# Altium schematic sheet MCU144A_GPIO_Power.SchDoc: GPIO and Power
size 431 x 279 mm; Date: Not shown in title block; ApprovedBy: Not shown in title block; CheckedBy: Not shown in title block; Author: Not shown in title block; CompanyName: Not shown in title block; DrawnBy: Gustavo Martinez; Engineer: Not shown in title block; Organization: Not shown in title block; Address1: Not shown in title block; Address2: Not shown in title block; Address3: Not shown in title block; Address4: Not shown in title block; DocumentNumber: 8; Revision: Use project parameter SCH_Rev; SheetNumber: 2; SheetTotal: 8; PageSetup: Record=PageOptions¦CenterHorizontal=True¦CenterVertical=True¦PrintScale=1.00¦XCorrection=1.00¦YCorrection=1.00¦PrintKind=0¦BorderSize=5000000¦LeftOffset=0¦BottomOffset=0¦Orientation=2¦PaperLength=1000¦PaperWidth=1000¦Scale=100¦PaperSource=15¦PrintQuality=600¦MediaType=1¦DitherType=10¦PaperKind=Letter¦PrintScaleMode=1
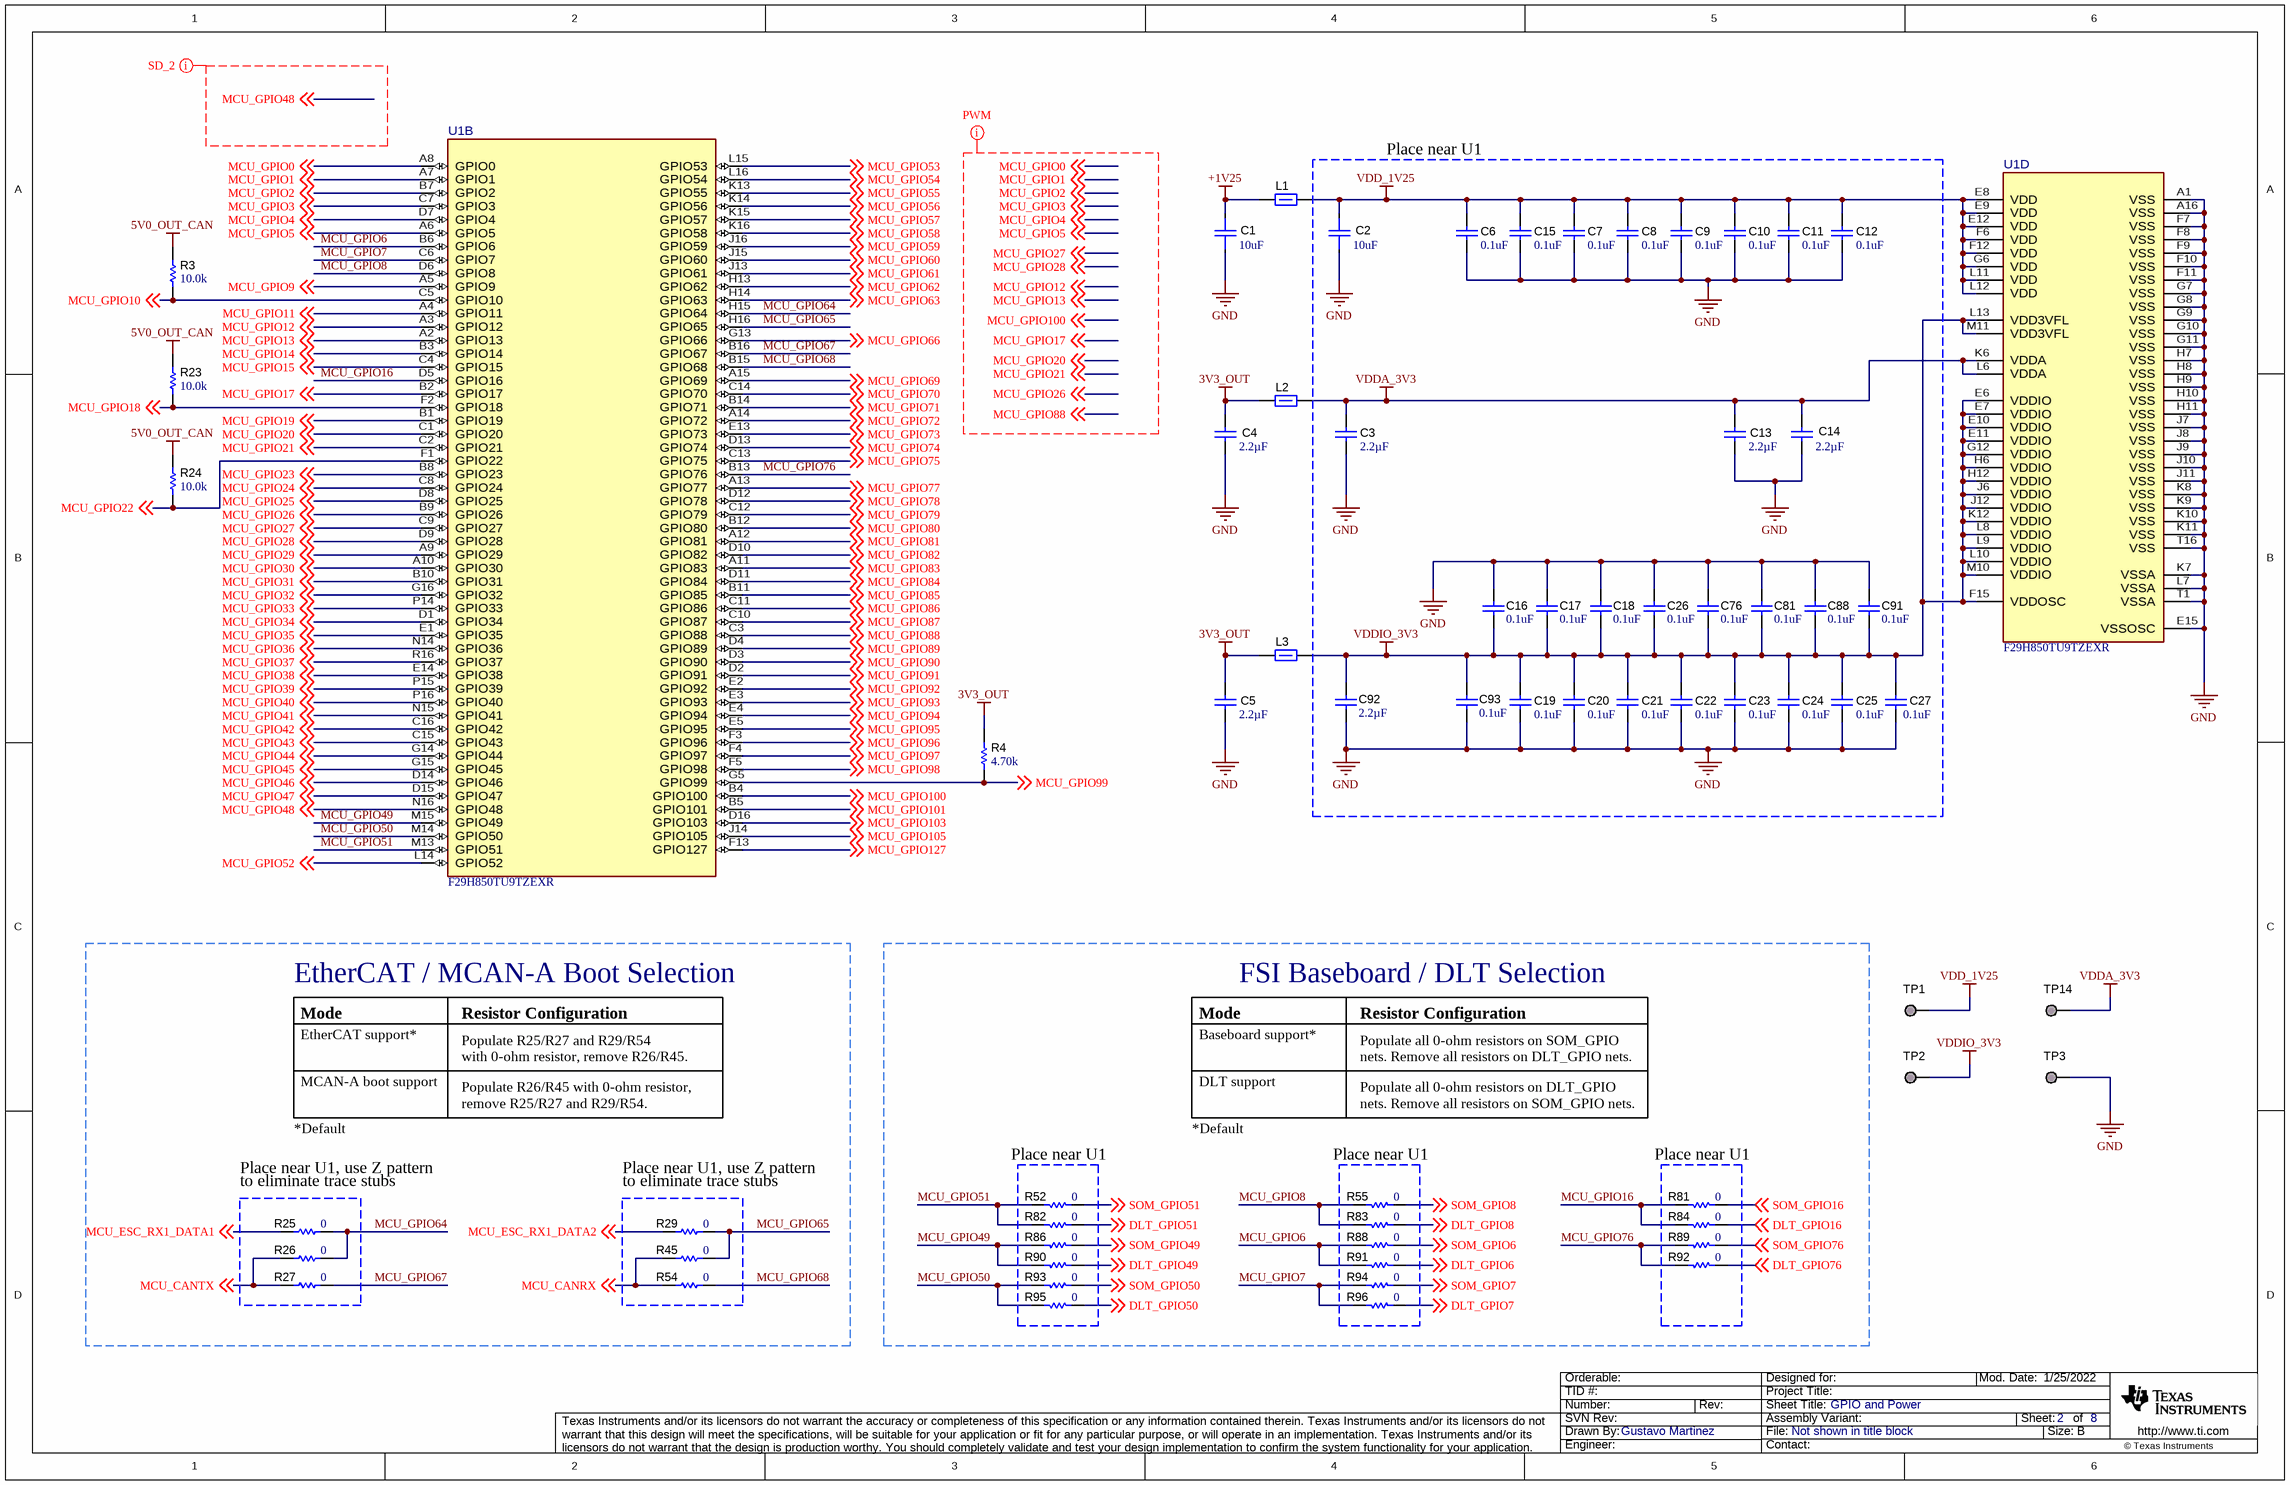
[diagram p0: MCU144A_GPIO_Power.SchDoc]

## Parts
C1  ValueDisplayed: 10uF  [FP-GRM155R61A106ME18D_0402-MFG]  (hidden comment: GRM155R61A106ME18D)
C2  ValueDisplayed: 10uF  [FP-GRM155R61A106ME18D_0402-MFG]  (hidden comment: GRM155R61A106ME18D)
C3  ValueDisplayed: 2.2µF  [0402]  (hidden comment: GRM155R61E225ME15D)
C4  ValueDisplayed: 2.2µF  [0402]  (hidden comment: GRM155R61E225ME15D)
C5  ValueDisplayed: 2.2µF  [0402]  (hidden comment: GRM155R61E225ME15D)
C6  ValueDisplayed: 0.1uF  [0402]  (hidden comment: GRM155R71E104KE14D)
C7  ValueDisplayed: 0.1uF  [0402]  (hidden comment: GRM155R71E104KE14D)
C8  ValueDisplayed: 0.1uF  [0402]  (hidden comment: GRM155R71E104KE14D)
C9  ValueDisplayed: 0.1uF  [0402]  (hidden comment: GRM155R71E104KE14D)
C10  ValueDisplayed: 0.1uF  [0402]  (hidden comment: GRM155R71E104KE14D)
C11  ValueDisplayed: 0.1uF  [0402]  (hidden comment: GRM155R71E104KE14D)
C12  ValueDisplayed: 0.1uF  [0402]  (hidden comment: GRM155R71E104KE14D)
C13  ValueDisplayed: 2.2µF  [0402]  (hidden comment: GRM155R61E225ME15D)
C14  ValueDisplayed: 2.2µF  [0402]  (hidden comment: GRM155R61E225ME15D)
C15  ValueDisplayed: 0.1uF  [0402]  (hidden comment: GRM155R71E104KE14D)
C16  ValueDisplayed: 0.1uF  [0402]  (hidden comment: GRM155R71E104KE14D)
C17  ValueDisplayed: 0.1uF  [0402]  (hidden comment: GRM155R71E104KE14D)
C18  ValueDisplayed: 0.1uF  [0402]  (hidden comment: GRM155R71E104KE14D)
C19  ValueDisplayed: 0.1uF  [0402]  (hidden comment: GRM155R71E104KE14D)
C20  ValueDisplayed: 0.1uF  [0402]  (hidden comment: GRM155R71E104KE14D)
C21  ValueDisplayed: 0.1uF  [0402]  (hidden comment: GRM155R71E104KE14D)
C22  ValueDisplayed: 0.1uF  [0402]  (hidden comment: GRM155R71E104KE14D)
C23  ValueDisplayed: 0.1uF  [0402]  (hidden comment: GRM155R71E104KE14D)
C24  ValueDisplayed: 0.1uF  [0402]  (hidden comment: GRM155R71E104KE14D)
C25  ValueDisplayed: 0.1uF  [0402]  (hidden comment: GRM155R71E104KE14D)
C26  ValueDisplayed: 0.1uF  [0402]  (hidden comment: GRM155R71E104KE14D)
C27  ValueDisplayed: 0.1uF  [0402]  (hidden comment: GRM155R71E104KE14D)
C76  ValueDisplayed: 0.1uF  [0402]  (hidden comment: GRM155R71E104KE14D)
C81  ValueDisplayed: 0.1uF  [0402]  (hidden comment: GRM155R71E104KE14D)
C88  ValueDisplayed: 0.1uF  [0402]  (hidden comment: GRM155R71E104KE14D)
C91  ValueDisplayed: 0.1uF  [0402]  (hidden comment: GRM155R71E104KE14D)
C92  ValueDisplayed: 2.2µF  [0402]  (hidden comment: GRM155R61E225ME15D)
C93  ValueDisplayed: 0.1uF  [0402]  (hidden comment: GRM155R71E104KE14D)
L1  BLM21PG221SN1D  [0805_HV]  (value not drawn)
L2  60ohm  [0603]  (value not drawn)
L3  60ohm  [0603]  (value not drawn)
R3  value 10.0k  [0402]  (hidden comment: AC0402FR-0710KL)
R4  ValueDisplayed: 4.70k  [0402]  (hidden comment: CRG0402F4K7)
R23  value 10.0k  [0402]  (hidden comment: AC0402FR-0710KL)
R24  value 10.0k  [0402]  (hidden comment: AC0402FR-0710KL)
R25  ValueDisplayed: 0  [0402]  (hidden comment: CRCW04020000Z0ED)
R26  ValueDisplayed: 0  [0402]  (hidden comment: CRCW04020000Z0ED)
R27  ValueDisplayed: 0  [0402]  (hidden comment: CRCW04020000Z0ED)
R29  ValueDisplayed: 0  [0402]  (hidden comment: CRCW04020000Z0ED)
R45  ValueDisplayed: 0  [0402]  (hidden comment: CRCW04020000Z0ED)
R52  ValueDisplayed: 0  [0402]  (hidden comment: CRCW04020000Z0ED)
R54  ValueDisplayed: 0  [0402]  (hidden comment: CRCW04020000Z0ED)
R55  ValueDisplayed: 0  [0402]  (hidden comment: CRCW04020000Z0ED)
R81  ValueDisplayed: 0  [0402]  (hidden comment: CRCW04020000Z0ED)
R82  ValueDisplayed: 0  [0402]  (hidden comment: CRCW04020000Z0ED)
R83  ValueDisplayed: 0  [0402]  (hidden comment: CRCW04020000Z0ED)
R84  ValueDisplayed: 0  [0402]  (hidden comment: CRCW04020000Z0ED)
R86  ValueDisplayed: 0  [0402]  (hidden comment: CRCW04020000Z0ED)
R88  ValueDisplayed: 0  [0402]  (hidden comment: CRCW04020000Z0ED)
R89  ValueDisplayed: 0  [0402]  (hidden comment: CRCW04020000Z0ED)
R90  ValueDisplayed: 0  [0402]  (hidden comment: CRCW04020000Z0ED)
R91  ValueDisplayed: 0  [0402]  (hidden comment: CRCW04020000Z0ED)
R92  ValueDisplayed: 0  [0402]  (hidden comment: CRCW04020000Z0ED)
R93  ValueDisplayed: 0  [0402]  (hidden comment: CRCW04020000Z0ED)
R94  ValueDisplayed: 0  [0402]  (hidden comment: CRCW04020000Z0ED)
R95  ValueDisplayed: 0  [0402]  (hidden comment: CRCW04020000Z0ED)
R96  ValueDisplayed: 0  [0402]  (hidden comment: CRCW04020000Z0ED)
TP1  CMP-0078143-4  [TESTPOINT]  (value not drawn)  (no BOM)
TP2  CMP-0078143-4  [TESTPOINT]  (value not drawn)  (no BOM)
TP3  CMP-0078143-4  [TESTPOINT]  (value not drawn)  (no BOM)
TP14  CMP-0078143-4  [TESTPOINT]  (value not drawn)  (no BOM)
U1  F29H850TU9TZEXR  [ZEX0256A-MFG]  (parts B,D of 4)

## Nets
3V3_OUT: C4.1 C5.1 L2.1 L3.1 R4.2
5V0_OUT_CAN: R3.2 R23.2 R24.2
+1V25: C1.2 L1.1
GND: C1.1 C2.1 C3.2 C4.2 C5.2 C6.2 C7.2 C8.2 C9.2 C10.2 C11.2 C12.2 C13.2 C14.2 C15.2 C16.2 C17.2 C18.2 C19.2 C20.2 C21.2 C22.2 C23.2 C24.2 C25.2 C26.2 C27.2 C76.2 C81.2 C88.2 C91.2 C92.1 C93.1 TP3.1 U1.A1(VSS) U1.A16(VSS) U1.E15(VSSOSC) U1.F7(VSS) U1.F8(VSS) U1.F9(VSS) U1.F10(VSS) U1.F11(VSS) U1.G7(VSS) U1.G8(VSS) U1.G9(VSS) U1.G10(VSS) U1.G11(VSS) U1.H7(VSS) U1.H8(VSS) U1.H9(VSS) U1.H10(VSS) U1.H11(VSS) U1.J7(VSS) U1.J8(VSS) U1.J9(VSS) U1.J10(VSS) U1.J11(VSS) U1.K7(VSSA) U1.K8(VSS) U1.K9(VSS) U1.K10(VSS) U1.K11(VSS) U1.L7(VSSA) U1.T1(VSSA) U1.T16(VSS)
VDD_1V25: C2.2 C6.1 C7.1 C8.1 C9.1 C10.1 C11.1 C12.1 C15.1 L1.2 TP1.1 U1.E8(VDD) U1.E9(VDD) U1.E12(VDD) U1.F6(VDD) U1.F12(VDD) U1.G6(VDD) U1.L11(VDD) U1.L12(VDD)
VDDA_3V3: C3.1 C13.1 C14.1 L2.2 TP14.1 U1.K6(VDDA) U1.L6(VDDA)
VDDIO_3V3: C16.1 C17.1 C18.1 C19.1 C20.1 C21.1 C22.1 C23.1 C24.1 C25.1 C26.1 C27.1 C76.1 C81.1 C88.1 C91.1 C92.2 C93.2 L3.2 TP2.1 U1.E6(VDDIO) U1.E7(VDDIO) U1.E10(VDDIO) U1.E11(VDDIO) U1.F15(VDDOSC) U1.G12(VDDIO) U1.H6(VDDIO) U1.H12(VDDIO) U1.J6(VDDIO) U1.J12(VDDIO) U1.K12(VDDIO) U1.L8(VDDIO) U1.L9(VDDIO) U1.L10(VDDIO) U1.L13(VDD3VFL) U1.M10(VDDIO) U1.M11(VDD3VFL)
DLT_GPIO6: R91.1 ; off-sheet DLT_GPIO6
DLT_GPIO7: R96.1 ; off-sheet DLT_GPIO7
DLT_GPIO8: R83.1 ; off-sheet DLT_GPIO8
DLT_GPIO16: R84.1 ; off-sheet DLT_GPIO16
DLT_GPIO49: R90.1 ; off-sheet DLT_GPIO49
DLT_GPIO50: R95.1 ; off-sheet DLT_GPIO50
DLT_GPIO51: R82.1 ; off-sheet DLT_GPIO51
DLT_GPIO76: R92.1 ; off-sheet DLT_GPIO76
MCU_CANRX: R45.1 R54.1 ; off-sheet MCU_CANRX
MCU_CANTX: R26.1 R27.1 ; off-sheet MCU_CANTX
MCU_ESC_RX1_DATA1: R25.1 ; off-sheet MCU_ESC_RX1_DATA1
MCU_ESC_RX1_DATA2: R29.1 ; off-sheet MCU_ESC_RX1_DATA2
MCU_GPIO0: U1.A8(GPIO0) ; off-sheet MCU_GPIO0
MCU_GPIO1: U1.A7(GPIO1) ; off-sheet MCU_GPIO1
MCU_GPIO2: U1.B7(GPIO2) ; off-sheet MCU_GPIO2
MCU_GPIO3: U1.C7(GPIO3) ; off-sheet MCU_GPIO3
MCU_GPIO4: U1.D7(GPIO4) ; off-sheet MCU_GPIO4
MCU_GPIO5: U1.A6(GPIO5) ; off-sheet MCU_GPIO5
MCU_GPIO6: R88.2 R91.2 U1.B6(GPIO6)
MCU_GPIO7: R94.2 R96.2 U1.C6(GPIO7)
MCU_GPIO8: R55.2 R83.2 U1.D6(GPIO8)
MCU_GPIO9: U1.A5(GPIO9) ; off-sheet MCU_GPIO9
MCU_GPIO10: R3.1 U1.C5(GPIO10) ; off-sheet MCU_GPIO10
MCU_GPIO11: U1.A4(GPIO11) ; off-sheet MCU_GPIO11
MCU_GPIO12: U1.A3(GPIO12) ; off-sheet MCU_GPIO12
MCU_GPIO13: U1.A2(GPIO13) ; off-sheet MCU_GPIO13
MCU_GPIO14: U1.B3(GPIO14) ; off-sheet MCU_GPIO14
MCU_GPIO15: U1.C4(GPIO15) ; off-sheet MCU_GPIO15
MCU_GPIO16: R81.2 R84.2 U1.D5(GPIO16)
MCU_GPIO17: U1.B2(GPIO17) ; off-sheet MCU_GPIO17
MCU_GPIO18: R23.1 U1.F2(GPIO18) ; off-sheet MCU_GPIO18
MCU_GPIO19: U1.B1(GPIO19) ; off-sheet MCU_GPIO19
MCU_GPIO20: U1.C1(GPIO20) ; off-sheet MCU_GPIO20
MCU_GPIO21: U1.C2(GPIO21) ; off-sheet MCU_GPIO21
MCU_GPIO22: R24.1 U1.F1(GPIO22) ; off-sheet MCU_GPIO22
MCU_GPIO23: U1.B8(GPIO23) ; off-sheet MCU_GPIO23
MCU_GPIO24: U1.C8(GPIO24) ; off-sheet MCU_GPIO24
MCU_GPIO25: U1.D8(GPIO25) ; off-sheet MCU_GPIO25
MCU_GPIO26: U1.B9(GPIO26) ; off-sheet MCU_GPIO26
MCU_GPIO27: U1.C9(GPIO27) ; off-sheet MCU_GPIO27
MCU_GPIO28: U1.D9(GPIO28) ; off-sheet MCU_GPIO28
MCU_GPIO29: U1.A9(GPIO29) ; off-sheet MCU_GPIO29
MCU_GPIO30: U1.A10(GPIO30) ; off-sheet MCU_GPIO30
MCU_GPIO31: U1.B10(GPIO31) ; off-sheet MCU_GPIO31
MCU_GPIO32: U1.G16(GPIO32) ; off-sheet MCU_GPIO32
MCU_GPIO33: U1.P14(GPIO33) ; off-sheet MCU_GPIO33
MCU_GPIO34: U1.D1(GPIO34) ; off-sheet MCU_GPIO34
MCU_GPIO35: U1.E1(GPIO35) ; off-sheet MCU_GPIO35
MCU_GPIO36: U1.N14(GPIO36) ; off-sheet MCU_GPIO36
MCU_GPIO37: U1.R16(GPIO37) ; off-sheet MCU_GPIO37
MCU_GPIO38: U1.E14(GPIO38) ; off-sheet MCU_GPIO38
MCU_GPIO39: U1.P15(GPIO39) ; off-sheet MCU_GPIO39
MCU_GPIO40: U1.P16(GPIO40) ; off-sheet MCU_GPIO40
MCU_GPIO41: U1.N15(GPIO41) ; off-sheet MCU_GPIO41
MCU_GPIO42: U1.C16(GPIO42) ; off-sheet MCU_GPIO42
MCU_GPIO43: U1.C15(GPIO43) ; off-sheet MCU_GPIO43
MCU_GPIO44: U1.G14(GPIO44) ; off-sheet MCU_GPIO44
MCU_GPIO45: U1.G15(GPIO45) ; off-sheet MCU_GPIO45
MCU_GPIO46: U1.D14(GPIO46) ; off-sheet MCU_GPIO46
MCU_GPIO47: U1.D15(GPIO47) ; off-sheet MCU_GPIO47
MCU_GPIO48: U1.N16(GPIO48) ; off-sheet MCU_GPIO48
MCU_GPIO49: R86.2 R90.2 U1.M15(GPIO49)
MCU_GPIO50: R93.2 R95.2 U1.M14(GPIO50)
MCU_GPIO51: R52.2 R82.2 U1.M13(GPIO51)
MCU_GPIO52: U1.L14(GPIO52) ; off-sheet MCU_GPIO52
MCU_GPIO53: U1.L15(GPIO53) ; off-sheet MCU_GPIO53
MCU_GPIO54: U1.L16(GPIO54) ; off-sheet MCU_GPIO54
MCU_GPIO55: U1.K13(GPIO55) ; off-sheet MCU_GPIO55
MCU_GPIO56: U1.K14(GPIO56) ; off-sheet MCU_GPIO56
MCU_GPIO57: U1.K15(GPIO57) ; off-sheet MCU_GPIO57
MCU_GPIO58: U1.K16(GPIO58) ; off-sheet MCU_GPIO58
MCU_GPIO59: U1.J16(GPIO59) ; off-sheet MCU_GPIO59
MCU_GPIO60: U1.J15(GPIO60) ; off-sheet MCU_GPIO60
MCU_GPIO61: U1.J13(GPIO61) ; off-sheet MCU_GPIO61
MCU_GPIO62: U1.H13(GPIO62) ; off-sheet MCU_GPIO62
MCU_GPIO63: U1.H14(GPIO63) ; off-sheet MCU_GPIO63
MCU_GPIO64: R25.2 R26.2 U1.H15(GPIO64)
MCU_GPIO65: R29.2 R45.2 U1.H16(GPIO65)
MCU_GPIO66: U1.G13(GPIO66) ; off-sheet MCU_GPIO66
MCU_GPIO67: R27.2 U1.B16(GPIO67)
MCU_GPIO68: R54.2 U1.B15(GPIO68)
MCU_GPIO69: U1.A15(GPIO69) ; off-sheet MCU_GPIO69
MCU_GPIO70: U1.C14(GPIO70) ; off-sheet MCU_GPIO70
MCU_GPIO71: U1.B14(GPIO71) ; off-sheet MCU_GPIO71
MCU_GPIO72: U1.A14(GPIO72) ; off-sheet MCU_GPIO72
MCU_GPIO73: U1.E13(GPIO73) ; off-sheet MCU_GPIO73
MCU_GPIO74: U1.D13(GPIO74) ; off-sheet MCU_GPIO74
MCU_GPIO75: U1.C13(GPIO75) ; off-sheet MCU_GPIO75
MCU_GPIO76: R89.2 R92.2 U1.B13(GPIO76)
MCU_GPIO77: U1.A13(GPIO77) ; off-sheet MCU_GPIO77
MCU_GPIO78: U1.D12(GPIO78) ; off-sheet MCU_GPIO78
MCU_GPIO79: U1.C12(GPIO79) ; off-sheet MCU_GPIO79
MCU_GPIO80: U1.B12(GPIO80) ; off-sheet MCU_GPIO80
MCU_GPIO81: U1.A12(GPIO81) ; off-sheet MCU_GPIO81
MCU_GPIO82: U1.D10(GPIO82) ; off-sheet MCU_GPIO82
MCU_GPIO83: U1.A11(GPIO83) ; off-sheet MCU_GPIO83
MCU_GPIO84: U1.D11(GPIO84) ; off-sheet MCU_GPIO84
MCU_GPIO85: U1.B11(GPIO85) ; off-sheet MCU_GPIO85
MCU_GPIO86: U1.C11(GPIO86) ; off-sheet MCU_GPIO86
MCU_GPIO87: U1.C10(GPIO87) ; off-sheet MCU_GPIO87
MCU_GPIO88: U1.C3(GPIO88) ; off-sheet MCU_GPIO88
MCU_GPIO89: U1.D4(GPIO89) ; off-sheet MCU_GPIO89
MCU_GPIO90: U1.D3(GPIO90) ; off-sheet MCU_GPIO90
MCU_GPIO91: U1.D2(GPIO91) ; off-sheet MCU_GPIO91
MCU_GPIO92: U1.E2(GPIO92) ; off-sheet MCU_GPIO92
MCU_GPIO93: U1.E3(GPIO93) ; off-sheet MCU_GPIO93
MCU_GPIO94: U1.E4(GPIO94) ; off-sheet MCU_GPIO94
MCU_GPIO95: U1.E5(GPIO95) ; off-sheet MCU_GPIO95
MCU_GPIO96: U1.F3(GPIO96) ; off-sheet MCU_GPIO96
MCU_GPIO97: U1.F4(GPIO97) ; off-sheet MCU_GPIO97
MCU_GPIO98: U1.F5(GPIO98) ; off-sheet MCU_GPIO98
MCU_GPIO99: R4.1 U1.G5(GPIO99) ; off-sheet MCU_GPIO99
MCU_GPIO100: U1.B4(GPIO100) ; off-sheet MCU_GPIO100
MCU_GPIO101: U1.B5(GPIO101) ; off-sheet MCU_GPIO101
MCU_GPIO103: U1.D16(GPIO103) ; off-sheet MCU_GPIO103
MCU_GPIO105: U1.J14(GPIO105) ; off-sheet MCU_GPIO105
MCU_GPIO127: U1.F13(GPIO127) ; off-sheet MCU_GPIO127
SOM_GPIO6: R88.1 ; off-sheet SOM_GPIO6
SOM_GPIO7: R94.1 ; off-sheet SOM_GPIO7
SOM_GPIO8: R55.1 ; off-sheet SOM_GPIO8
SOM_GPIO16: R81.1 ; off-sheet SOM_GPIO16
SOM_GPIO49: R86.1 ; off-sheet SOM_GPIO49
SOM_GPIO50: R93.1 ; off-sheet SOM_GPIO50
SOM_GPIO51: R52.1 ; off-sheet SOM_GPIO51
SOM_GPIO76: R89.1 ; off-sheet SOM_GPIO76

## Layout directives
net class SD_2: MCU_GPIO48
net class PWM: MCU_GPIO0, MCU_GPIO1, MCU_GPIO2, MCU_GPIO3, MCU_GPIO4, MCU_GPIO5, MCU_GPIO12, MCU_GPIO13, MCU_GPIO17, MCU_GPIO20, MCU_GPIO21, MCU_GPIO26, MCU_GPIO27, MCU_GPIO28, MCU_GPIO88, MCU_GPIO100

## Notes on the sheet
- Place near U1
- EtherCAT / MCAN-A Boot Selection
- Mode
- Resistor Configuration
- FSI Baseboard / DLT Selection
- EtherCAT support*
- MCAN-A boot support
- Populate R25/R27 and R29/R54
  with 0-ohm resistor, remove R26/R45.
- Populate R26/R45 with 0-ohm resistor, remove R25/R27 and R29/R54.
- Baseboard support*
- DLT support
- Populate all 0-ohm resistors on SOM_GPIO nets. Remove all resistors on DLT_GPIO nets.
- Populate all 0-ohm resistors on DLT_GPIO nets. Remove all resistors on SOM_GPIO nets.
- *Default
- Place near U1, use Z pattern
- (near R25) to eliminate trace stubs
- (near R29) to eliminate trace stubs

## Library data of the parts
C1 C2 = CMP-0120207-1: 10 µF ±20% 10V Ceramic Capacitor X5R 0402 (1005 Metric); Manufacturer: Murata; Cap_F: 10µF; TempCo: 15%; SizeZ_mm: 0.7mm; Value: 10µF; AEC Qualified: No
C3-C5 C13 C14 C92 = CMP-0081010-1: CAP, CERM, 2.2 µF, 25 V,+/- 20%, X5R, 0402; Manufacturer: MuRata; TaMin_C: -55°C; Polarized: N; SizeAreaWB_mm2: 3; U/M: EA; Value: 2.2uF; TaMax_C: 85°C; SizeZ_mm: 0.6; SizeX_mm: 1; SizeY_mm: 0.5; Value2: 25V; AEC Category: Q200
C6-C12 C15-C27 C76 C81 C88 C91 C93 = CMP-0006659-2: CAP, CERM, 0.1 uF, 25 V, +/- 10%, X7R, 0402; Manufacturer: MuRata; TaMin_C: -55°C; Polarized: N; SizeAreaWB_mm2: 3; Value1: Unknown; U/M: EA; Value: 0.1uF; TaMax_C: 125°C; SizeZ_mm: 0.6; SizeX_mm: 1; SizeY_mm: 0.5; Value2: 25V; Cap_F: 100nF; AEC Category: Q200
L1 = CMP-0003363-1: Ferrite Bead, 220 ohm @ 100 MHz, 2 A, 0805; Manufacturer: MuRata; ZTyp@100MHz_Ohm: 220; SizeAreaWB_mm2: 6.75; DCR_ohm: 0.045; Value1: 0.045 ohm; Value: 220 ohm; Imax_A: 2A; SizeZ_mm: 1.45; SizeX_mm: 2; SizeY_mm: 1.25; SizeArea_mm2: 2.5
L2 L3 = CMP-0003173-2: Ferrite Bead, 60 ohm @ 100 MHz, 3 A, 0603; Manufacturer: Wurth Elektronik; PartNumber: 742792602; Ztyp@1GHz_Ohm: 110.436; ZTyp@100MHz_Ohm: 60; SizeAreaWB_mm2: 4.68; DCR_ohm: 0.04; Value1: 0.04 ohm; Imax_A: 3A; SizeZ_mm: 1; SizeX_mm: 1.6; SizeY_mm: 0.8; SizeArea_mm2: 1.28
R3 R23 R24 = CMP-0077731-1: RES, 10.0 k, 1%, 0.063 W, AEC-Q200 Grade 0, 0402; Manufacturer: Yageo America; Power_W: 63mW; TempCo: 100 ppm/C; Value_Code: 10k0; U/M: EA; EIA_Code: E96; Res_ohm: 10k; SizeX_mm: 1.0; SizeY_mm: 0.5; SizeZ_mm: 0.6; Value2: 0.063W; AEC Qualified: Y; VDC_V: 50V; AEC Grade: 0; AEC Category: Q200
R4 = CMP-0026631-1: RES, 4.70 k, 1%, 0.063 W, 0402; Manufacturer: TE Connectivity; Power_W: 63mW; TempCo: 100 ppm/C; Value_Code: 4k70; U/M: EA; Value: 4.70k; Res_ohm: 4.7k; SizeX_mm: 1; SizeY_mm: 0.5; SizeZ_mm: 0.6; Value2: 0.063W; AEC Qualified: N; AEC Category: Q200
R25-R27 R29 R45 R52 R54 R55 R81-R84 R86 R88-R96 = CMP-0026822-3: RES, 0, 5%, 0.063 W, AEC-Q200 Grade 0, 0402; Manufacturer: Vishay-Dale; Power_W: 63mW; TempCo: 200 ppm/C; Value_Code: 0000; Value: 0; EIA_Code: E24; SizeX_mm: 1; SizeY_mm: 0.5; SizeZ_mm: 0.6; Value2: 0.063W; AEC Qualified: Y; AEC Category: Q200; VDC_V: 50V
TP1-TP3 TP14 = CMP-0078143-4: TEST POINT.  No entry in BOM.
U1 = CMP-0121934-2: Real-Time Microcontroller; Manufacturer: Texas Instruments; SizeZ_mm: 1.3mm; AEC Qualified: No; Core Architecture: C29x; Data Bus Width: 64bits; Frequency_Fixed: 200MHz; Interface: I2C,SPI,UART,CAN,LIN,IrDA,Other; Max Supply Voltage: 3.63V; Memory Size: 4MBytes; Memory Type: FLASH; Min Supply Voltage: 1.14V; Number Of A/D Converters: 5; Number Of Cores: 3; Number Of Ethernet Channels: 1; Number Of I2C Channels: 2; Number Of Pwm Channels: 36; Number Of Timers/Counters: 12; Number Of Uart Channels: 6; Ram Size: 452KBytes; Standoff Height: 0.25mm; TaMax_C: +105°C; TaMin_C: -40°C; TJmax_C: +125°C; AEC Category: Q200; CompType: IC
